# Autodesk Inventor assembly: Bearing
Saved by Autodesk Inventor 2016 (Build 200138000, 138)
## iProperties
Created: 2015-08
Part Number: Bearing
Document SubType Name: Assembly
Designer: Ugljesa
Mass: 72.9462 g
Surface Area: 85.1408 cm^2
Volume: 9.29251 cm^3
Density: 7.85 g/cm^3
ClientObjectVersion: 1
Author: Ugljesa
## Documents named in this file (2)
- C:\Users\Ugljesa\Desktop\Turbokompr\Assembly1\Design Accelerator\Bearing3.iam
- C:\Users\Ugljesa\Documents\Inventor\Content Center Files\R2016\en-US\BS 292 (V)\BS 292_ Part 1 - N 1005 - 25 x 47 x 12.ipt
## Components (1 placed, 1 different names)
1. BS 292: Part 1 (V) (Metric) N 1005 - 25 x 47 x 12:1
